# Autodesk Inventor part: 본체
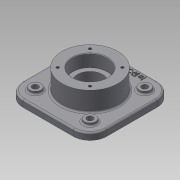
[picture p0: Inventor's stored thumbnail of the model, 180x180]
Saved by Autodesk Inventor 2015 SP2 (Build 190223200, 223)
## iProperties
Created: 2015-07
Part Number: 본체
Material: 일반
Document SubType Name: Modeling
Designer: AMC
Density: 1 g/cm^3
Appearance: 기본값
Author: AMC
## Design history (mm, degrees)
sketch "스케치1"
  geometry: L1 (-75, -75)-(75, -75); L2 (75, -75)-(75, 75); L3 (75, 75)-(-75, 75); L4 (-75, 75)-(-75, -75); L5 (-75, -75)-(75, 75); L6 (75, -75)-(-75, 75); 1 further point
  constraints: 12 end point, 2 midpoint, 2 parallel, 1 horizontal, 1 perpendicular
  dimensions: "d0" = 150 distance of L3.end L2.end; "d1" = 150 distance of L2.end L1.end
extrude "돌출1" new body sketch "스케치1" distance "d2" = 12; taper "d3" = 0 deg
sketch "스케치2"
  geometry: C1 r 50 at (0, 0); 1 further point
  constraints: 1 centre point, 1 coincident
  dimensions: "d4" = 100 diameter of C1
extrude "돌출2" join sketch "스케치2" distance "d5" = 47; taper "d7" = 0 deg; dims "d6" = 23, "d8" = 0
hole "구멍1" diameter "d11" = 45; stored, may be unused: countersink angle "d15" = 90 deg, drill point angle "d17" = 0 deg; dims "d9" = 10, "d10" = 10, "d12" = 6, "d13" = 62, "d14" = 22, "d16" = 48
hole "구멍2" diameter "d20" = 62; stored, may be unused: countersink angle "d24" = 90 deg, drill point angle "d26" = 0 deg; dims "d18" = 10, "d19" = 10, "d21" = 6, "d22" = 62, "d23" = 22, "d25" = 22
sketch "스케치3"
  geometry: C1 r 10 at (-49, 49); C2 r 10 at (49, 49); C3 r 10 at (-49, -49); C4 r 10 at (49, -49); 1 further point
  constraints: 4 centre point, 2 horizontal alignment
  dimensions: "d27" = 20 diameter of C1; "d28" = 20 diameter of C2; "d29" = 20 diameter of C3; "d30" = 20 diameter of C4; "d31" = 49 horizontal distance of C1.centre point (0, 0); "d32" = 49 horizontal distance of C2.centre point (0, 0); "d33" = 49 horizontal distance of C3.centre point (0, 0); "d34" = 49 horizontal distance of point (0, 0) C4.centre; "d35" = 49 horizontal distance of C2.centre point (0, 0); "d36" = 49 horizontal distance of C4.centre point (0, 0)
extrude "돌출3" join sketch "스케치3" distance "d37" = 5; taper "d38" = 0 deg
fillet "모깎기1" dims "d39" = 30
sketch "스케치4"
  geometry: L1 (0, 0)-(41, 0); L2 (0, 0)-(28.991, 28.991); A1 r 41 centre (0, 0) between (41, 0) and (28.991, 28.991); 2 further points
  constraints: 4 end point, 2 coincident, 2 point on circle, 1 centre point, 1 horizontal
  dimensions: "d40" = 82 diameter of A1; "d41" = 45 deg angle of L1 L2
hole "구멍3" sketch "스케치4" at (28.991, 28.991) diameter "d42" = 4.917; stored, may be unused: countersink angle "d46" = 90 deg, drill point angle "d48" = 118 deg; dims "d43" = 10, "d44" = 62, "d45" = 22, "d47" = 13
sketch "스케치5"
  geometry: L1 (0, 0)-(41, 0); L2 (0, 0)-(28.991, 28.991); A1 r 41 centre (0, 0) between (41, 0) and (28.991, 28.991); 2 further points
  constraints: 4 end point, 2 coincident, 2 point on circle, 1 centre point, 1 horizontal
  dimensions: "d52" = 82 diameter of A1; "d53" = 45 deg angle of L1 L2
hole "구멍4" sketch "스케치5" at (28.991, 28.991) diameter "d54" = 4.917; stored, may be unused: countersink angle "d58" = 90 deg, drill point angle "d60" = 118 deg; dims "d55" = 10, "d56" = 62, "d57" = 22, "d59" = 13
hole "구멍5" diameter "d66" = 11; stored, may be unused: countersink angle "d70" = 90 deg, drill point angle "d72" = 0 deg; dims "d64" = 10, "d65" = 10, "d67" = 10, "d68" = 62, "d69" = 22, "d71" = 13
hole "구멍6" diameter "d75" = 11; stored, may be unused: countersink angle "d79" = 90 deg, drill point angle "d81" = 0 deg; dims "d73" = 10, "d74" = 10, "d76" = 10, "d77" = 62, "d78" = 22, "d80" = 13
hole "구멍7" diameter "d84" = 11; stored, may be unused: countersink angle "d88" = 90 deg, drill point angle "d90" = 0 deg; dims "d82" = 10, "d83" = 10, "d85" = 10, "d86" = 62, "d87" = 22, "d89" = 13
hole "구멍8" diameter "d93" = 11; stored, may be unused: countersink angle "d97" = 90 deg, drill point angle "d99" = 0 deg; dims "d91" = 10, "d92" = 10, "d94" = 10, "d95" = 62, "d96" = 22, "d98" = 13
chamfer "모따기1" distance "d100" = 1; stored, may be unused: second distance "d101" = 2, angle "d102" = 45 deg
fillet "모깎기2" dims "d103" = 3
fillet "모깎기3" dims "d104" = 3
fillet "모깎기4" dims "d105" = 3
fillet "모깎기5" dims "d106" = 0.3
sketch "스케치6"
  geometry: 2 further points
  constraints: 1 vertical alignment, 1 other
  dimensions: "d107" = 65 distance of point (0, 0) point (0, 65)
feature "엠보싱1" sketch "스케치6" dims "d0" = 150, "d1" = 150, "d108" = 1, "d109" = 0
node "솔리드1"
pattern_circular "원형 패턴1" dims angle "d50" = 360 deg
pattern_circular "원형 패턴2" dims angle "d62" = 360 deg
